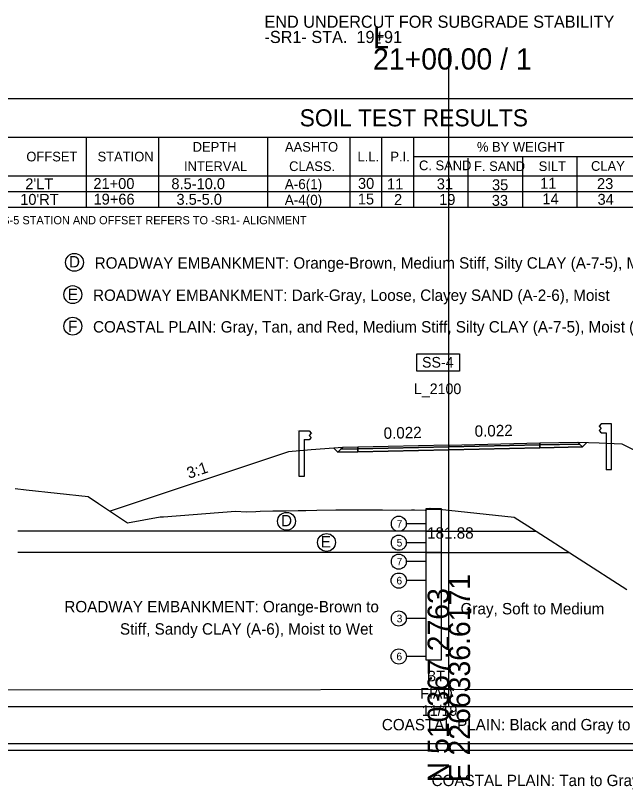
# Model space of a CAD drawing. Extents: x -827 to 2303, y -169 to 9934.
# Drawn here: x 1092.9 to 1173.3, y -10.9 to 91.1 of the extents above; entities that cross this region are included whole.
import ezdxf

# ---------------------------------------------------------------- set-up
doc = ezdxf.new("R2010")
doc.units = 0
for name, color, linetype in [('Exist Cross Section Cell', 7, 'Continuous'), ('Exist XS Center Line Elevation Label', 7, 'Continuous'), ('Exist XS Ground Line', 7, 'Continuous'), ('Geotech Sheets and Borders Cell', 7, 'Continuous'), ('Prop CMT Guardrail Graphics', 7, 'Continuous'), ('Prop CMT Pvmt Course 1', 7, 'Continuous'), ('Prop CMT Pvmt Course 2', 7, 'Continuous'), ('Prop CMT Pvmt Course 3', 7, 'Continuous'), ('Prop CMT Pvmt Surface', 7, 'Continuous'), ('Prop CMT Pvmt Surface Shoulder', 7, 'Continuous'), ('Prop CMT Shld Paved Course 1', 7, 'Continuous'), ('Prop CMT Shld Paved Course 2', 7, 'Continuous'), ('Prop CMT Shld Paved Course 3', 7, 'Continuous'), ('Prop CMT Slope Grass', 7, 'Continuous'), ('Prop CMT Subgrade Earthwork', 7, 'Continuous'), ('Prop DirtTable_ Soil Test Results - Tx (Sample Data)', 7, 'Continuous'), ('Prop Road Sect_ Boring - Header (Sample Box + Tx)', 7, 'Continuous'), ('Prop Road Sect_ Boring - Header Labels from Geopak', 7, 'Continuous'), ('Prop Road Sect_ Boring - Material (Outline)', 7, 'Continuous'), ('Prop Road Sect_ Boring - Peripheral (SPT Oval + Leader)', 7, 'Continuous'), ('Prop Road Sect_ Boring - Peripheral (SPT Tx)', 7, 'Continuous'), ('Prop Road Sect_ Material - Bubble + Leader + Bubble Tx', 7, 'Continuous'), ('Prop Road Sect_ Material - Contact (General - Major)', 7, 'Continuous'), ('Prop Road Sect_ Material - Contact (General - Minor)', 7, 'Continuous'), ('Prop Road Sect_ Material - Tx (Composite Desc)', 7, 'Continuous'), ('Prop Road Sect_ Recs - UC (Tx)', 7, 'Continuous'), ('Prop XS SE Text', 7, 'Continuous'), ('Prop XS Side Slope Text', 7, 'Continuous'), ('Scratch_Level_0', 7, 'Continuous')]:
    doc.layers.add(name, color=color, linetype=linetype)

msp = doc.modelspace()

# ---------------------------------------------------------------- linework, layer by layer
at = {"layer": 'Exist Cross Section Cell'}
for p, q in [((1150, 0), (1150, 86.78)), ((1000, 0), (1150, 0)), ((1150, 0), (1300, 0))]:
    msp.add_line(p, q, dxfattribs=at)
at = {"layer": 'Exist XS Ground Line'}
msp.add_lwpolyline([(1092.84, 28.73), (1094.26, 28.57), (1102.45, 27.68), (1103.82, 26.76), (1107.64, 24.2), (1111.94, 24.99), (1112.4, 25.03), (1121.89, 25.74), (1123.3, 25.69), (1124.57, 25.73), (1125.13, 25.74), (1126.78, 25.78), (1127.61, 25.79), (1128.54, 25.81), (1130.12, 25.85), (1131.16, 25.86), (1132.61, 25.88), (1135.12, 25.92), (1137.51, 25.93), (1138.98, 25.94), (1140.2, 25.95), (1141.25, 25.94), (1142.94, 25.91), (1145.09, 25.94), (1145.46, 25.93), (1146.88, 25.91), (1147.54, 26.16), (1150, 25.88), (1158.6, 24.96), (1160.88, 23.51), (1173.45, 15.42)], dxfattribs=at)
at = {"layer": 'Geotech Sheets and Borders Cell'}
for p, q in [((1083.9, 80.16), (1211.7, 80.16)), ((1083.9, 75.06), (1211.7, 75.06)), ((1102.19, 75.06), (1102.19, 67.9)), ((1111.71, 75.06), (1111.71, 67.9)), ((1126.08, 75.06), (1126.08, 67.9)), ((1136.93, 75.06), (1136.93, 67.9)), ((1141.13, 75.06), (1141.13, 67.9)), ((1145.33, 75.06), (1145.33, 67.9)), ((1145.33, 72.51), (1193.67, 72.51)), ((1159.71, 72.51), (1159.71, 67.9)), ((1166.91, 67.9), (1166.91, 72.51)), ((1152.52, 72.31), (1152.52, 67.9)), ((1083.9, 69.96), (1211.7, 69.96)), ((1083.9, 69.96), (1211.7, 69.96)), ((1083.9, 67.9), (1211.7, 67.9)), ((1083.9, 67.9), (1211.7, 67.9)), ((1083.9, 67.9), (1211.7, 67.9)), ((1083.9, 67.9), (1211.7, 67.9)), ((1102.19, 67.9), (1102.19, 65.84)), ((1111.71, 67.9), (1111.71, 65.84)), ((1126.08, 67.9), (1126.08, 65.84)), ((1136.93, 67.9), (1136.93, 65.84)), ((1141.13, 67.9), (1141.13, 65.84)), ((1145.33, 67.9), (1145.33, 65.84)), ((1152.52, 67.9), (1152.52, 65.84)), ((1159.71, 67.9), (1159.71, 65.84)), ((1166.91, 65.84), (1166.91, 67.9)), ((1083.9, 65.84), (1211.7, 65.84)), ((1083.9, 65.84), (1211.7, 65.84))]:
    msp.add_line(p, q, dxfattribs=at)
at = {"layer": 'Prop CMT Guardrail Graphics'}
for points in [[(1171.42, 37.25), (1170.09, 37.25), (1169.81, 36.96)], [(1169.81, 36.96), (1170.09, 36.67)], [(1171.42, 31.25), (1171.42, 37.25)], [(1130.26, 30.34), (1130.26, 36.34)], [(1130.26, 36.34), (1131.59, 36.34), (1131.86, 36.05)], [(1131.86, 36.05), (1131.59, 35.75)], [(1131.59, 35.75), (1131.86, 35.46)], [(1170.09, 36.67), (1169.81, 36.38)], [(1169.81, 36.38), (1170.09, 36.08), (1170.75, 36.08)], [(1170.75, 36.08), (1170.75, 31.25)], [(1131.86, 35.46), (1131.59, 35.17), (1130.93, 35.17)], [(1130.93, 35.17), (1130.93, 30.34)], [(1170.75, 31.25), (1171.42, 31.25)], [(1130.93, 30.34), (1130.26, 30.34)]]:
    msp.add_lwpolyline(points, dxfattribs=at)
at = {"layer": 'Prop CMT Pvmt Course 1'}
for points in [[(1150, 34.48), (1162, 34.75)], [(1162, 34.75), (1162, 34.5)], [(1150, 34.48), (1138, 34.21)], [(1138, 33.96), (1150, 34.23)], [(1138, 34.21), (1138, 33.96)], [(1162, 34.5), (1150, 34.23)], [(1150, 34.23), (1150, 34.48)], [(1150, 34.23), (1150, 34.48)]]:
    msp.add_lwpolyline(points, dxfattribs=at)
msp.add_lwpolyline([(1150, 34.23), (1150, 34.35), (1150, 34.35), (1150, 34.23)], close=True, dxfattribs=at)
msp.add_lwpolyline([(1150, 34.23), (1150, 34.35), (1150, 34.35), (1150, 34.23)], close=True, dxfattribs=at)
at = {"layer": 'Prop CMT Pvmt Course 2'}
for points in [[(1138, 33.96), (1150, 34.23)], [(1150, 34.23), (1138, 33.96)], [(1138, 33.96), (1138, 33.96)], [(1162, 34.5), (1150, 34.23)], [(1150, 34.23), (1162, 34.5)], [(1150, 34.23), (1150, 34.23)], [(1150, 34.23), (1150, 34.23)], [(1162, 34.5), (1162, 34.5)]]:
    msp.add_lwpolyline(points, dxfattribs=at)
at = {"layer": 'Prop CMT Pvmt Course 3'}
for points in [[(1150, 34.23), (1138, 33.96)], [(1138, 33.96), (1138, 33.59)], [(1138, 33.59), (1150, 33.85)], [(1150, 34.23), (1162, 34.5)], [(1150, 33.85), (1150, 34.23)], [(1150, 33.85), (1150, 34.23)], [(1162, 34.12), (1150, 33.85)], [(1162, 34.5), (1162, 34.12)]]:
    msp.add_lwpolyline(points, dxfattribs=at)
at = {"layer": 'Prop CMT Pvmt Surface'}
for points in [[(1150, 34.48), (1162, 34.75)], [(1150, 34.48), (1138, 34.21)]]:
    msp.add_lwpolyline(points, dxfattribs=at)
at = {"layer": 'Prop CMT Pvmt Surface Shoulder'}
for points in [[(1162, 34.75), (1167, 34.86)], [(1138, 34.21), (1136, 34.17)]]:
    msp.add_lwpolyline(points, dxfattribs=at)
at = {"layer": 'Prop CMT Shld Paved Course 1'}
for points in [[(1162, 34.75), (1167, 34.86), (1167.24, 34.61)], [(1162, 34.5), (1162, 34.75)], [(1138, 34.21), (1136, 34.17), (1135.74, 33.91)], [(1135.74, 33.91), (1138, 33.96)], [(1138, 33.96), (1138, 34.21)], [(1167.24, 34.61), (1162, 34.5)]]:
    msp.add_lwpolyline(points, dxfattribs=at)
at = {"layer": 'Prop CMT Shld Paved Course 2'}
for points in [[(1138, 33.96), (1135.74, 33.91)], [(1135.74, 33.91), (1138, 33.96)], [(1135.74, 33.91), (1135.74, 33.91)], [(1138, 33.96), (1138, 33.96)], [(1162, 34.5), (1167.24, 34.61)], [(1167.24, 34.61), (1162, 34.5)], [(1162, 34.5), (1162, 34.5)], [(1167.24, 34.61), (1167.24, 34.61)]]:
    msp.add_lwpolyline(points, dxfattribs=at)
at = {"layer": 'Prop CMT Shld Paved Course 3'}
for points in [[(1135.74, 33.91), (1135.36, 33.53)], [(1138, 33.96), (1135.74, 33.91)], [(1135.74, 33.91), (1135.74, 33.91)], [(1138, 33.59), (1138, 33.96)], [(1162, 34.5), (1167.24, 34.61)], [(1162, 34.12), (1162, 34.5)], [(1167.61, 34.25), (1162, 34.12)], [(1167.24, 34.61), (1167.24, 34.61)], [(1167.24, 34.61), (1167.61, 34.25)], [(1135.36, 33.53), (1138, 33.59)]]:
    msp.add_lwpolyline(points, dxfattribs=at)
at = {"layer": 'Prop CMT Slope Grass'}
for points in [[(1167, 34.86), (1169.81, 34.75)], [(1169.81, 34.75), (1172.81, 34.64)], [(1131.86, 33.84), (1128.86, 33.6)], [(1136, 34.17), (1131.86, 33.84)], [(1172.81, 34.64), (1237.93, 2.08)], [(1128.86, 33.6), (1105.33, 25.75)]]:
    msp.add_lwpolyline(points, dxfattribs=at)
at = {"layer": 'Prop CMT Subgrade Earthwork'}
for points in [[(1167.61, 34.25), (1168.18, 34.81)], [(1135.36, 33.53), (1134.82, 34.07)], [(1150, 33.85), (1138, 33.59)], [(1150, 33.85), (1162, 34.12)], [(1162, 34.12), (1167.61, 34.25)], [(1138, 33.59), (1135.36, 33.53)]]:
    msp.add_lwpolyline(points, dxfattribs=at)
at = {"layer": 'Prop Road Sect_ Boring - Header (Sample Box + Tx)'}
msp.add_lwpolyline([(1145.79, 46.52), (1151.39, 46.52), (1151.39, 44.21), (1145.79, 44.21)], close=True, dxfattribs=at)
at = {"layer": 'Prop Road Sect_ Boring - Material (Outline)'}
for points in [[(1147, 26.1), (1149, 26.1), (1149, 26), (1147, 26)], [(1147, 26.1), (1149, 26.1), (1149, 26), (1147, 26)], [(1147, 26), (1149, 26), (1149, 23.1), (1147, 23.1)], [(1147, 26), (1149, 26), (1149, 23.1), (1147, 23.1)], [(1147, 23.1), (1149, 23.1), (1149, 20.3), (1147, 20.3)], [(1147, 23.1), (1149, 23.1), (1149, 20.3), (1147, 20.3)], [(1147, 20.3), (1149, 20.3), (1149, 6.1), (1147, 6.1)], [(1147, 20.3), (1149, 20.3), (1149, 6.1), (1147, 6.1)]]:
    msp.add_lwpolyline(points, close=True, dxfattribs=at)
at = {"layer": 'Prop Road Sect_ Boring - Peripheral (SPT Oval + Leader)'}
for p, q in [((1147, 24.1), (1144.38, 24.1)), ((1147, 21.6), (1144.38, 21.6)), ((1147, 19.1), (1144.38, 19.1)), ((1147, 16.6), (1144.41, 16.6)), ((1147, 11.6), (1144.38, 11.6)), ((1147, 6.6), (1144.41, 6.6))]:
    msp.add_line(p, q, dxfattribs=at)
for centre, major_axis, ratio in [((1143.4, 24.1), (0, 1), 0.983465), ((1143.4, 21.6), (0, 1), 0.983465), ((1143.4, 19.1), (0, 1), 0.983465), ((1143.4, 16.6), (1.01, 0), 0.992963), ((1143.4, 11.6), (0, 1), 0.983465), ((1143.4, 6.6), (1.01, 0), 0.992963)]:
    msp.add_ellipse(centre, major_axis=major_axis, ratio=ratio, dxfattribs=at)
at = {"layer": 'Prop Road Sect_ Material - Bubble + Leader + Bubble Tx'}
for centre in [(1100.64, 58.56), (1100.42, 54.31), (1100.42, 50.14), (1128.6, 24.42), (1133.87, 21.63)]:
    msp.add_circle(centre, 1.18, dxfattribs=at)
at = {"layer": 'Prop Road Sect_ Material - Contact (General - Major)'}
msp.add_line((1012.4, 2.13), (1232.52, 2.35), dxfattribs=at)
at = {"layer": 'Prop Road Sect_ Material - Contact (General - Minor)'}
for p, q in [((1147, 23.1), (1093.16, 23.1)), ((1149, 23.1), (1161.51, 23.1)), ((1147, 20.3), (1093.16, 20.3)), ((1149, 20.3), (1165.86, 20.3)), ((1267.35, -4.9), (1089.13, -4.9)), ((1267.61, -5.8), (1089.13, -5.8))]:
    msp.add_line(p, q, dxfattribs=at)

# ---------------------------------------------------------------- texts
at = {"layer": 'Exist Cross Section Cell'}
for s, p in [('L', (1140, 86.78)), ('21+00.00 / 1', (1140, 83.98))]:
    msp.add_text(s, height=2.8, dxfattribs=at).set_placement(p)
for s, p in [('E 2266336.6171', (1152.8, -10)), ('N 510367.2763', (1150, -10))]:
    msp.add_text(s, height=2.8, rotation=90, dxfattribs=at).set_placement(p)
at = {"layer": 'Exist XS Center Line Elevation Label'}
msp.add_text('181.88', height=1.5, dxfattribs=at).set_placement((1147.13, 22.13))
at = {"layer": 'Geotech Sheets and Borders Cell'}
for s, height, p in [('SOIL TEST RESULTS', 2.25, (1130.33, 76.49)), ('DEPTH', 1.275, (1116.23, 73.15)), ('AASHTO', 1.275, (1128.39, 73.15)), ('% BY WEIGHT', 1.275, (1153.7, 73.15)), ('OFFSET', 1.275, (1094.3, 71.87)), ('STATION', 1.275, (1103.69, 71.87)), ('L.L.', 1.275, (1137.96, 71.87)), ('P.I.', 1.275, (1142.29, 71.87)), ('INTERVAL', 1.275, (1115.08, 70.6)), ('CLASS.', 1.275, (1128.94, 70.6)), ('C. SAND', 1.275, (1146.06, 70.71)), ('F. SAND', 1.275, (1153.32, 70.6)), ('SILT', 1.275, (1161.84, 70.6)), ('CLAY', 1.275, (1168.74, 70.63))]:
    msp.add_text(s, height=height, dxfattribs=at).set_placement(p)
at = {"layer": 'Prop DirtTable_ Soil Test Results - Tx (Sample Data)'}
for s, height, p in [("2'LT", 1.44, (1094.16, 68.2)), ('21+00', 1.44, (1103.14, 68.23)), ('8.5-10.0', 1.44, (1113.42, 68.21)), ('A-6(1)', 1.327, (1128.37, 68.21)), ('30', 1.44, (1138.02, 68.25)), ('11', 1.44, (1141.85, 68.18)), ('31', 1.44, (1148.41, 68.19)), ('35', 1.44, (1155.69, 68.07)), ('11', 1.44, (1162.03, 68.27)), ('23', 1.44, (1169.53, 68.22)), ("10'RT", 1.44, (1093.49, 66.14)), ('19+66', 1.44, (1103.16, 66.17)), ('3.5-5.0', 1.44, (1114.09, 66.15)), ('A-4(0)', 1.327, (1128.37, 66.14)), ('15', 1.44, (1138, 66.19)), ('2', 1.44, (1142.77, 66.12)), ('19', 1.44, (1148.72, 66.13)), ('33', 1.44, (1155.66, 66.01)), ('14', 1.44, (1162.33, 66.21)), ('34', 1.44, (1169.6, 66.15)), ('* NOTE: SS-5 STATION AND OFFSET REFERS TO -SR1- ALIGNMENT', 1.08, (1084.39, 63.58))]:
    msp.add_text(s, height=height, dxfattribs=at).set_placement(p)
at = {"layer": 'Prop Road Sect_ Boring - Header (Sample Box + Tx)'}
msp.add_text('SS-4', height=1.4, dxfattribs=at).set_placement((1146.46, 44.69))
at = {"layer": 'Prop Road Sect_ Boring - Header Labels from Geopak'}
for s, p in [('L_2100', (1145.39, 41.19)), ('BT', (1147.09, 3.32)), ('FIAD', (1146.23, 1.04)), ('11/19', (1146.43, -1.23))]:
    msp.add_text(s, height=1.4, dxfattribs=at).set_placement(p)
at = {"layer": 'Prop Road Sect_ Boring - Peripheral (SPT Tx)'}
for s, p in [('7', (1143.12, 23.6)), ('5', (1143.12, 21.1)), ('7', (1143.12, 18.6)), ('6', (1143.09, 16.1)), ('3', (1143.12, 11.1)), ('6', (1143.09, 6.1))]:
    msp.add_text(s, height=1, dxfattribs=at).set_placement(p)
at = {"layer": 'Prop Road Sect_ Material - Tx (Composite Desc)'}
for s, p in [('D', (1099.92, 57.89)), ('ROADWAY EMBANKMENT: Orange-Brown, Medium Stiff, Silty CLAY (A-7-5), Moist', (1103.31, 57.73)), ('E', (1099.76, 53.58)), ('ROADWAY EMBANKMENT: Dark-Gray, Loose, Clayey SAND (A-2-6), Moist', (1103.09, 53.48)), ('F', (1099.81, 49.36)), ('COASTAL PLAIN: Gray, Tan, and Red, Medium Stiff, Silty CLAY (A-7-5), Moist (Black Creek Formation)', (1103.09, 49.31)), ('D', (1127.88, 23.76)), ('E', (1133.11, 20.97)), ('ROADWAY EMBANKMENT: Orange-Brown to ', (1099.31, 12.42)), ('Gray, Soft to Medium ', (1151.54, 12.15)), ('Stiff, Sandy CLAY (A-6), Moist to Wet', (1106.64, 9.48)), ('COASTAL PLAIN: Black and Gray to Orange-Brown and Gray, Soft, Sandy SILT (A-4), Moist (Black Creek Formation)', (1141.16, -3.14)), ('COASTAL PLAIN: Tan to Gray with Red, Loose, Clayey SAND (A-2-6), Moist (Black Creek Formation)', (1147.72, -10.49))]:
    msp.add_text(s, height=1.5, dxfattribs=at).set_placement(p)
at = {"layer": 'Prop Road Sect_ Recs - UC (Tx)'}
for s, p in [('END UNDERCUT FOR SUBGRADE STABILITY', (1125.69, 89.49)), ('-SR1- STA.  19+91', (1125.69, 87.48)), ('+', (1140.28, 87.68)), ('-', (1140.39, 86.87))]:
    msp.add_text(s, height=1.6, dxfattribs=at).set_placement(p)
at = {"layer": 'Prop XS SE Text'}
for p in [(1141.41, 35.29), (1153.41, 35.56)]:
    msp.add_text('0.022', height=1.5, rotation=1.273, dxfattribs=at).set_placement(p)
at = {"layer": 'Prop XS Side Slope Text'}
msp.add_text('3:1', height=1.5, rotation=18.4332, dxfattribs=at).set_placement((1115.73, 30.01))
at = {"layer": 'Scratch_Level_0'}
for s, p in [('RT_GR_Graphics Out 01', (1169.63, 36.95)), ('RT_GR_Graphics Out 02', (1169.89, 37.24)), ('RT_GR_Graphics Out 03', (1171.23, 37.24)), ('LT_GR_Graphics Out 03', (1130.07, 36.33)), ('LT_GR_Graphics Out 02', (1131.4, 36.33)), ('LT_GR_Graphics Out 09', (1131.4, 35.74)), ('LT_GR_Graphics Out 01', (1131.68, 36.04)), ('RT_GR_Graphics Out 08', (1169.62, 36.37)), ('RT_GR_Graphics Out 09', (1169.89, 36.66)), ('RT_GR_Graphics Out 07', (1169.89, 36.07)), ('RT_GR_Graphics Out 06', (1170.56, 36.07)), ('LT_GR_Graphics Out 06', (1130.73, 35.16)), ('LT_GR_Graphics Out 07', (1131.4, 35.16)), ('LT_GR_Graphics Out 08', (1131.67, 35.45)), ('RT_PV1_OEOT', (1161.91, 34.74)), ('RT_PS1_OEOP', (1166.91, 34.85)), ('RT_Sub_Trench_Out_DLT', (1167.98, 34.8)), ('RT_GS_OS_GR_Face_Graphics', (1169.59, 34.74)), ('LT_GS_OS_GR_Face_Graphics', (1131.64, 33.83)), ('LT_Sub_Trench_Out_DLT', (1134.62, 34.06)), ('LT_PS3_Shelf_Out', (1135.6, 33.9)), ('LT_PS3_OEOP', (1135.65, 33.9)), ('LT_PS2_OEOP', (1135.65, 33.9)), ('LT_PS1_OEOP', (1135.91, 34.16)), ('LT_PV3_OEOT', (1137.9, 33.95)), ('LT_PV2_OEOT', (1137.9, 33.95)), ('LT_PV1_OEOT', (1137.91, 34.2)), ('RT_PV2_OEEOP', (1149.89, 34.22)), ('RT_PV3_OEEOP', (1149.89, 34.22)), ('LT_Sub_OEEOP', (1149.89, 33.84)), ('RT_Sub_OEEOP', (1149.89, 33.84)), ('RT_PV1_OEEOP', (1149.9, 34.34)), ('LT_PV1_OEEOP', (1149.9, 34.34)), ('RT_PV2_IEEOP', (1149.9, 34.22)), ('LT_PV2_IEEOP', (1149.9, 34.22)), ('LT_PV2_OEEOP', (1149.89, 34.22)), ('LT_PV3_OEEOP', (1149.89, 34.22)), ('RT_PV1_IEEOP', (1149.9, 34.34)), ('LT_PV1_IEEOP', (1149.91, 34.34)), ('PV2_PGL', (1149.94, 34.22)), ('PV1_PGL', (1149.94, 34.47)), ('RT_PV3_OEOT', (1161.9, 34.49)), ('RT_PV2_OEOT', (1161.9, 34.49)), ('RT_Sub_OEOT', (1161.9, 34.11)), ('RT_PS3_Shelf_Out', (1167.1, 34.6)), ('RT_PS3_OEOP', (1167.15, 34.6)), ('RT_PS2_OEOP', (1167.15, 34.6)), ('RT_Sub_Trench_Out', (1167.45, 34.24)), ('RT_GS_OS_CTL', (1172.71, 34.63)), ('LT_GS_OS_CTL', (1128.76, 33.59)), ('LT_Sub_Trench_Out', (1135.2, 33.52)), ('LT_Sub_OEOT', (1137.9, 33.58)), ('RT_GR_Graphics Out 05', (1170.56, 31.24)), ('RT_GR_Graphics Out 04', (1171.23, 31.24)), ('LT_GR_Graphics Out 04', (1130.07, 30.33)), ('LT_GR_Graphics Out 05', (1130.74, 30.33)), ('LT_Slope_Fill', (1105.24, 25.74))]:
    msp.add_text(s, height=0.02, dxfattribs=at).set_placement(p)

doc.saveas('drawing.dxf')
